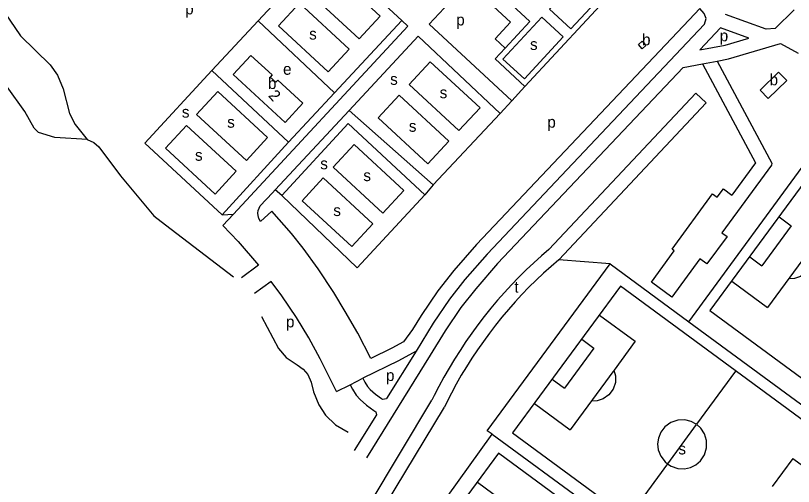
# Model space of a CAD drawing. Extents: x 155696 to 157795, y 382328 to 384028.
# Drawn here: x 156139.1 to 156412.1, y 383161.2 to 383326.5 of the extents above; entities that cross this region are included whole.
import ezdxf

# ---------------------------------------------------------------- set-up
doc = ezdxf.new("R2010")
doc.units = 0
for name, color, linetype in [('BLT_Basislijn', 7, 'Continuous'), ('BLT_Bebouwing', 7, 'Continuous'), ('BLT_Centroide', 7, 'Continuous'), ('BLT_Huisnummer', 7, 'Continuous'), ('BLT_Vlakafsluiter', 7, 'Continuous')]:
    doc.layers.add(name, color=color, linetype=linetype)

msp = doc.modelspace()

# ---------------------------------------------------------------- linework, layer by layer
at = {"layer": 'BLT_Basislijn'}
for p, q in [((156297.81, 383338.07), (156284.28, 383323.47)), ((156375.47, 383324.98), (156379.27, 383328.99)), ((156412.41, 383328.52), (156405.67, 383321.95)), ((156402.56, 383321.78), (156388.25, 383326.85)), ((156207.98, 383307.16), (156224.22, 383324.63)), ((156224.22, 383324.63), (156251.07, 383299.39)), ((156251.07, 383299.39), (156274.66, 383324.73)), ((156274.66, 383324.73), (156276.77, 383322.72)), ((156313.31, 383296.58), (156284.28, 383323.47)), ((156396.52, 383318.61), (156386.55, 383322.14)), ((156405.67, 383321.95), (156402.56, 383321.78)), ((156388.11, 383316.12), (156396.52, 383318.61)), ((156379.29, 383314.47), (156388.11, 383316.12)), ((156389.28, 383311.25), (156407.59, 383316.68)), ((156373.44, 383308.28), (156380.18, 383309.55)), ((156380.18, 383309.55), (156385.34, 383310.51)), ((156385.34, 383310.51), (156389.28, 383311.25)), ((156207.98, 383307.16), (156234.88, 383282.01)), ((156317.89, 383301.55), (156313.31, 383296.58)), ((156251.07, 383299.39), (156234.88, 383282.01)), ((156326.25, 383244.39), (156377.89, 383299.26)), ((156377.89, 383299.26), (156381.53, 383295.84)), ((156329.72, 383240.77), (156381.53, 383295.84)), ((156232.49, 383263.34), (156230.24, 383265.3)), ((156211.6, 383256.49), (156215.59, 383256.82)), ((156211.81, 383252.75), (156215.59, 383256.82)), ((156407.09, 383255.83), (156411.31, 383252.73)), ((156211.81, 383252.75), (156217.18, 383247.17)), ((156411.31, 383252.73), (156401, 383238.69)), ((156217.18, 383247.17), (156224.36, 383238.87)), ((156418.38, 383244.89), (156403.05, 383224.01)), ((156396.77, 383241.79), (156401, 383238.69)), ((156224.36, 383238.87), (156218.33, 383234.45)), ((156228.84, 383233.12), (156222.99, 383228.97)), ((156390.49, 383233.23), (156403.05, 383224.01)), ((156344.04, 383221.37), (156356.6, 383212.15)), ((156375.37, 383218.99), (156437.42, 383173.47)), ((156337.81, 383212.88), (156342.03, 383209.78)), ((156356.6, 383212.15), (156349.16, 383202.03)), ((156279.67, 383208.7), (156269.28, 383192.02)), ((156342.03, 383209.78), (156331.72, 383195.74)), ((156284.64, 383207.23), (156262.22, 383171.24)), ((156349.1, 383201.94), (156333.77, 383181.06)), ((156391.81, 383201.69), (156378.15, 383183.08)), ((156251.71, 383194.5), (156256.54, 383196.9)), ((156256.54, 383196.9), (156261, 383199.16)), ((156327.49, 383198.84), (156331.72, 383195.74)), ((156236.89, 383111.16), (156285.18, 383191.45)), ((156241.1, 383108.46), (156289.58, 383189.06)), ((156321.21, 383190.28), (156333.77, 383181.06)), ((156265.72, 383186.31), (156257.94, 383173.83)), ((156378.04, 383182.93), (156367.93, 383169.17)), ((156306.4, 383179.59), (156394.72, 383114.76)), ((156411.92, 383171.06), (156404.69, 383161.22)), ((156411.92, 383171.06), (156424.8, 383161.6)), ((156367.93, 383169.17), (156354.22, 383150.48)), ((156301.22, 383162.67), (156313.78, 383153.45))]:
    msp.add_line(p, q, dxfattribs=at)
for points in [[(156133.91, 383382.3), (156133.71, 383380.28), (156131.34, 383377.09), (156130.46, 383373.16), (156130.34, 383371.89), (156129.91, 383344.51), (156130.36, 383339.27), (156131.42, 383334.63), (156135.24, 383327.43), (156140.74, 383319.44), (156151.17, 383309.15), (156153.79, 383305.53), (156155.8, 383300.75), (156158.03, 383292.1), (156159.95, 383288.2), (156164.2, 383283)], [(156321.57, 383363.69), (156350.49, 383336.86), (156317.89, 383301.55)], [(156164.2, 383283), (156152.82, 383283.67), (156147.05, 383285.45), (156145.57, 383286.94), (156142.3, 383292.79), (156136.05, 383301.51), (156129.07, 383312.72), (156115.62, 383332.62), (156109.7, 383342.22), (156108.74, 383344.44), (156108.5, 383345.28), (156108.38, 383346.1), (156108.43, 383347.69), (156108.66, 383349.03), (156109.1, 383350.25), (156109.72, 383351.3), (156110.6, 383352.33), (156112.44, 383354.74), (156113.48, 383356.73), (156114.26, 383359.07), (156113.28, 383360.98)], [(156247.6, 383349.79), (156224.22, 383324.63)], [(156274.66, 383324.73), (156247.6, 383349.79)], [(156310.91, 383315.02), (156319.62, 383324.43), (156301.09, 383341.62)], [(156297.81, 383338.07), (156312.81, 383324.17), (156307.4, 383318.33), (156310.91, 383315.02)], [(156378.8, 383321.22), (156380.95, 383323.49), (156381.45, 383325.45), (156380.79, 383327.26), (156379.27, 383328.99)], [(156375.47, 383324.98), (156300.88, 383246.13), (156292.92, 383236.99), (156287.33, 383229.91), (156281.48, 383221.17), (156278.45, 383216.24)], [(156276.77, 383322.72), (156215.59, 383256.82)], [(156378.8, 383321.22), (156304.58, 383242.77), (156296.77, 383233.8), (156291.37, 383226.97), (156285.69, 383218.47), (156279.67, 383208.7)], [(156386.55, 383322.14), (156379.29, 383314.47)], [(156256.18, 383293.2), (156280.44, 383319.28)], [(156280.44, 383319.28), (156309.15, 383292.08)], [(156317.89, 383301.55), (156307.45, 383311.3), (156310.91, 383315.02)], [(156407.59, 383316.68), (156413.77, 383313.27)], [(156385.34, 383310.51), (156404.51, 383274.73), (156404.44, 383273.95), (156387.05, 383250.25), (156388.85, 383248.98), (156381.73, 383239.29), (156379.29, 383241.08), (156369.42, 383227.64), (156362.25, 383232.86), (156370.31, 383243.89), (156369.57, 383244.47), (156383.71, 383263.94), (156385.33, 383262.76), (156387.53, 383265.66), (156390.54, 383263.46)], [(156380.18, 383309.55), (156398.83, 383274.75), (156390.54, 383263.46)], [(156211.6, 383256.49), (156184.49, 383281.76), (156207.98, 383307.16)], [(156373.44, 383308.28), (156308.29, 383239.41), (156300.62, 383230.6), (156295.42, 383224.02), (156289.9, 383215.77), (156284.64, 383207.23)], [(156313.31, 383296.58), (156309.15, 383292.08)], [(156230.24, 383265.3), (156256.18, 383293.2)], [(156256.18, 383293.2), (156285.62, 383267.08)], [(156309.15, 383292.08), (156285.62, 383267.08)], [(156282.79, 383263.59), (156255.83, 383288.63), (156232.49, 383263.34)], [(156164.2, 383283), (156166.54, 383281.89), (156168.23, 383280.44), (156175.95, 383270.24), (156187.6, 383256.2), (156191.67, 383253.01), (156215.61, 383234.72)], [(156234.88, 383282.01), (156211.6, 383256.49)], [(156375.37, 383218.99), (156420.05, 383279.86)], [(156224.99, 383254.16), (156224.42, 383255.23), (156224.2, 383256.3), (156224.14, 383257.18), (156224.27, 383258.12), (156224.52, 383258.9), (156224.93, 383259.75), (156229.25, 383264.23), (156230.24, 383265.3)], [(156285.62, 383267.08), (156282.79, 383263.59)], [(156232.49, 383263.34), (156259.01, 383237.93)], [(156259.01, 383237.93), (156282.79, 383263.59)], [(156250.83, 383229.32), (156245.33, 383237.64), (156240.01, 383244.86), (156235.89, 383249.98), (156229.05, 383257.84), (156224.99, 383254.16)], [(156326.25, 383244.39), (156323.72, 383242.19), (156321, 383239.73), (156318.33, 383237.21), (156315.73, 383234.63), (156313.18, 383231.99), (156310.7, 383229.3), (156308.27, 383226.55), (156305.91, 383223.74), (156303.61, 383220.89), (156301.38, 383217.98), (156299.21, 383215.02), (156297.11, 383212.02), (156295.08, 383208.96), (156293.12, 383205.87), (156291.22, 383202.73), (156289.4, 383199.55), (156287.65, 383196.32), (156285.98, 383193.07), (156285.18, 383191.45)], [(156418.42, 383244.94), (156418.93, 383242.96), (156418.89, 383240.68), (156418.12, 383238.35), (156416.64, 383236.33), (156414.65, 383234.9), (156412.49, 383234.18), (156410.44, 383234.08)], [(156329.72, 383240.77), (156327.03, 383238.45), (156324.39, 383236.06), (156321.81, 383233.62), (156319.29, 383231.12), (156316.82, 383228.56), (156314.41, 383225.95), (156312.06, 383223.28), (156309.77, 383220.57), (156307.54, 383217.8), (156305.38, 383214.98), (156303.28, 383212.11), (156301.24, 383209.2), (156299.27, 383206.24), (156297.37, 383203.24), (156295.54, 383200.2), (156293.77, 383197.11), (156292.07, 383193.99), (156290.45, 383190.83), (156289.58, 383189.06)], [(156306.4, 383179.59), (156304.62, 383180.71), (156347.78, 383239.3)], [(156347.78, 383239.3), (156375.37, 383218.99)], [(156251.71, 383194.5), (156245.93, 383206.03), (156242.04, 383213.41), (156237.66, 383220.5), (156232.53, 383228.08), (156228.84, 383233.12)], [(156263.76, 383206.07), (156259.23, 383215.01), (156254.77, 383222.6), (156250.83, 383229.32)], [(156225.36, 383220.85), (156231.35, 383209.66), (156234.08, 383206.49), (156237.88, 383203.86), (156239.97, 383202.41), (156241.68, 383200.48), (156242.83, 383197.81), (156243.65, 383194.38), (156245.5, 383189.82), (156247.91, 383186.23), (156251.37, 383182.84), (156255.76, 383180.26)], [(156278.45, 383216.24), (156275.19, 383211.93), (156271.18, 383209.69), (156263.76, 383206.07)], [(156279.67, 383208.7), (156273.49, 383205.26), (156261, 383199.16)], [(156349.14, 383201.99), (156349.65, 383200.01), (156349.61, 383197.73), (156348.84, 383195.4), (156347.36, 383193.38), (156345.37, 383191.95), (156343.21, 383191.23), (156341.16, 383191.13)], [(156256.54, 383196.9), (156257.34, 383195.32), (156258.61, 383193.25), (156260.06, 383191.66), (156262.26, 383189.72), (156264.79, 383187.86), (156265.56, 383187.39), (156265.72, 383186.31)], [(156261, 383199.16), (156261.71, 383197.76), (156262.62, 383196.27), (156263.58, 383195.23), (156265.4, 383193.61), (156267.57, 383192.02), (156267.86, 383191.84), (156269.28, 383192.02)], [(156378.01, 383183.06), (156376.28, 383184.01), (156374.04, 383184.57), (156371.55, 383184.48), (156369.11, 383183.65), (156367.04, 383182.15), (156365.55, 383180.22), (156364.72, 383178.15), (156364.45, 383176.15), (156364.67, 383174.01), (156365.53, 383171.8), (156367.07, 383169.79), (156367.93, 383169.17)], [(156367.93, 383169.17), (156369.17, 383168.28), (156371.57, 383167.48), (156373.94, 383167.39), (156376.04, 383167.87), (156377.84, 383168.78), (156379.53, 383170.24), (156380.88, 383172.27), (156381.62, 383174.72), (156381.62, 383177.3), (156380.89, 383179.68), (156379.63, 383181.61), (156378.17, 383182.95)], [(156351.43, 383055.23), (156263.35, 383119.54), (156306.4, 383179.59)]]:
    msp.add_lwpolyline(points, dxfattribs=at)
for points in [[(156249.62, 383342.46), (156267.1, 383326.33), (156259.7, 383318.32), (156242.22, 383334.45)], [(156340.21, 383343.5), (156326.52, 383328.72), (156334.02, 383321.87), (156347.69, 383336.61)], [(156238.75, 383330.85), (156256.22, 383314.72), (156248.82, 383306.71), (156231.35, 383322.84)], [(156323.86, 383325.97), (156310.17, 383311.19), (156317.67, 383304.33), (156331.34, 383319.07)], [(156284.63, 383310.25), (156302.1, 383294.12), (156294.7, 383286.11), (156277.23, 383302.24)], [(156210.03, 383299.82), (156227.5, 383283.69), (156220.11, 383275.67), (156202.63, 383291.8)], [(156273.69, 383298.59), (156291.17, 383282.46), (156283.77, 383274.45), (156266.3, 383290.58)], [(156199.03, 383287.96), (156216.51, 383271.83), (156209.11, 383263.82), (156191.64, 383279.95)], [(156257.93, 383281.24), (156275.41, 383265.11), (156268.01, 383257.1), (156250.53, 383273.23)], [(156382.81, 383222.98), (156463.79, 383163.35), (156501.71, 383214.86), (156420.73, 383274.48)], [(156247.06, 383269.51), (156264.53, 383253.38), (156257.13, 383245.37), (156239.66, 383261.5)], [(156313.53, 383180.03), (156394.51, 383120.41), (156432.43, 383171.91), (156351.45, 383231.53)], [(156270.71, 383121.33), (156351.69, 383061.7), (156389.61, 383113.21), (156308.63, 383172.83)]]:
    msp.add_lwpolyline(points, close=True, dxfattribs=at)
at = {"layer": 'BLT_Bebouwing'}
msp.add_line((156406.91, 383306.62), (156400.45, 383300.36), dxfattribs=at)
for points in [[(156357.72, 383316.31), (156359.03, 383317.48), (156360.32, 383316.03), (156359, 383314.86)], [(156215.48, 383305.75), (156221.68, 383312.49), (156229.09, 383305.66), (156228.41, 383304.92), (156230.43, 383303.06), (156231.1, 383303.8), (156239.88, 383295.71), (156233.65, 383288.98)]]:
    msp.add_lwpolyline(points, close=True, dxfattribs=at)
msp.add_lwpolyline([(156400.45, 383300.36), (156403.27, 383297.41), (156409.76, 383303.67), (156406.91, 383306.62)], dxfattribs=at)
at = {"layer": 'BLT_Vlakafsluiter'}
msp.add_line((156347.78, 383239.3), (156329.72, 383240.77), dxfattribs=at)

# ---------------------------------------------------------------- texts
at = {"layer": 'BLT_Centroide'}
for s, p in [('p', (156198.59, 383326.91)), ('p', (156293.75, 383323.03)), ('s', (156242.11, 383318.07)), ('b', (156358.99, 383316.08)), ('p', (156386.26, 383317.46)), ('s', (156319.66, 383314.43)), ('e', (156232.96, 383305.72)), ('b', (156403.77, 383302.03)), ('b', (156227.67, 383300.72)), ('s', (156270.55, 383302.18)), ('s', (156287.94, 383297.47)), ('s', (156197.43, 383290.66)), ('s', (156213.34, 383287.12)), ('p', (156325.74, 383287.14)), ('s', (156277.11, 383285.7)), ('s', (156202.05, 383275.52)), ('s', (156246.03, 383272.55)), ('s', (156261.15, 383268.38)), ('s', (156250.61, 383256.12)), ('t', (156314.16, 383229.21)), ('p', (156233.99, 383217.03)), ('p', (156269.1, 383198.22)), ('s', (156371.74, 383172.43))]:
    msp.add_text(s, height=4, dxfattribs=at).set_placement(p)
at = {"layer": 'BLT_Huisnummer'}
msp.add_text('2', height=4, rotation=312.7716, dxfattribs=at).set_placement((156227.57, 383298.22))

doc.saveas('drawing.dxf')
